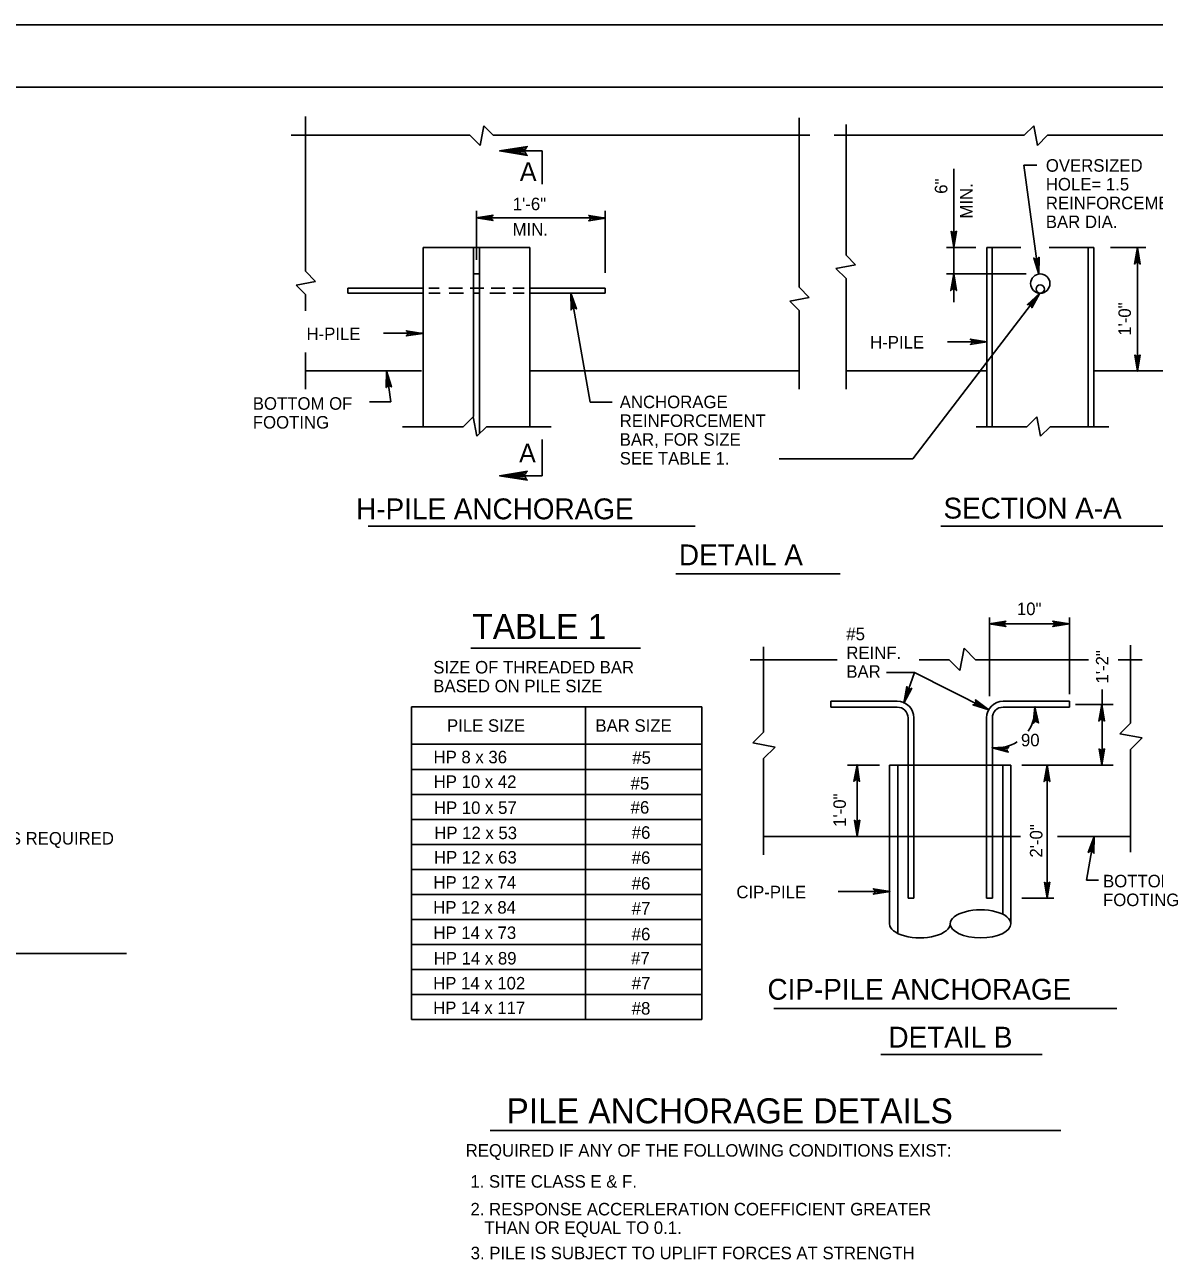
# Model space of a CAD drawing. Extents: x 235 to 2276, y 116 to 1308.
# Drawn here: x 807.5 to 1078.3, y 1007.6 to 1304.4 of the extents above; entities that cross this region are included whole.
import ezdxf

# ---------------------------------------------------------------- set-up
doc = ezdxf.new("R2010")
doc.units = 0
doc.layers.add('1', color=7, linetype='Continuous')
doc.layers.add('PLT-BNDY', color=7, linetype='Continuous')

msp = doc.modelspace()

# ---------------------------------------------------------------- linework, layer by layer
at = {"layer": '1'}
for p, q in [((619.42, 1289.41), (1405.42, 1289.41)), ((874.85, 1282.4), (874.85, 1245.3)), ((916.71, 1275.49), (917.59, 1280.19)), ((917.59, 1280.19), (919.86, 1277.92)), ((993.2, 1282.1), (993.2, 1241.47)), ((1004.46, 1249.13), (1004.46, 1280.51)), ((1049.45, 1280.19), (1047.18, 1277.92)), ((1050.33, 1275.49), (1049.45, 1280.19)), ((871.43, 1277.92), (914.28, 1277.92)), ((914.28, 1277.92), (916.71, 1275.49)), ((919.86, 1277.92), (995.76, 1277.92)), ((1047.18, 1277.92), (1001.63, 1277.92)), ((1052.76, 1277.92), (1050.33, 1275.49)), ((1095.6, 1277.92), (1052.76, 1277.92)), ((921.38, 1274.16), (931.58, 1274.16)), ((931.58, 1266.17), (931.58, 1274.16)), ((1047.03, 1270.76), (1050.19, 1270.76)), ((1047.03, 1270.76), (1050.5, 1245.42)), ((1030.27, 1250.97), (1030.27, 1269.87)), ((915.84, 1248.05), (915.84, 1259.82)), ((946.67, 1244.9), (946.67, 1259.82)), ((915.84, 1258.07), (946.67, 1258.07)), ((903.03, 1250.97), (903.03, 1207.98)), ((903.03, 1250.97), (928.65, 1250.97)), ((915.16, 1250.97), (915.16, 1210.43)), ((915.23, 1250.97), (916.46, 1250.97)), ((916.53, 1250.97), (916.53, 1206.54)), ((928.65, 1250.97), (928.65, 1207.98)), ((1028.52, 1250.97), (1035.59, 1250.97)), ((1030.27, 1244.65), (1030.27, 1250.97)), ((1038.19, 1250.97), (1038.19, 1207.98)), ((1038.19, 1250.97), (1046.38, 1250.97)), ((1039.51, 1250.97), (1039.51, 1207.98)), ((1053.15, 1250.97), (1063.81, 1250.97)), ((1062.49, 1250.97), (1062.49, 1207.98)), ((1063.81, 1250.97), (1063.81, 1207.98)), ((1067.81, 1250.97), (1076.29, 1250.97)), ((1074.31, 1221.39), (1074.31, 1250.97)), ((1002.03, 1245.97), (1006.73, 1246.86)), ((1006.73, 1246.86), (1004.46, 1249.13)), ((874.85, 1245.3), (877.28, 1242.87)), ((915.16, 1244.65), (916.53, 1244.65)), ((1004.46, 1243.54), (1002.03, 1245.97)), ((1028.52, 1244.65), (1047.6, 1244.65)), ((1030.27, 1237.92), (1030.27, 1244.65)), ((877.28, 1242.87), (872.58, 1241.99)), ((872.58, 1241.99), (874.85, 1239.72)), ((885.02, 1241.26), (903.03, 1241.26)), ((885.02, 1241.26), (885.02, 1240.03)), ((904.43, 1241.26), (906.87, 1241.26)), ((909.21, 1241.26), (912.47, 1241.26)), ((914.32, 1241.26), (917.58, 1241.26)), ((919.37, 1241.26), (922.63, 1241.26)), ((924.54, 1241.26), (927.28, 1241.26)), ((928.65, 1241.26), (946.67, 1241.26)), ((946.67, 1241.26), (946.67, 1240.03)), ((993.2, 1241.47), (995.63, 1239.04)), ((1004.46, 1217.04), (1004.46, 1243.54)), ((874.85, 1239.72), (874.85, 1235.82)), ((885.02, 1240.03), (903.03, 1240.03)), ((904.43, 1240.03), (907.11, 1240.03)), ((909.27, 1240.03), (912.72, 1240.03)), ((915.16, 1240.03), (916.53, 1240.03)), ((919, 1240.03), (922.82, 1240.03)), ((924.67, 1240.03), (927.28, 1240.03)), ((928.65, 1240.03), (946.67, 1240.03)), ((943.08, 1213.88), (938.61, 1239.3)), ((995.63, 1239.04), (990.93, 1238.16)), ((990.93, 1238.16), (993.2, 1235.89)), ((1020.47, 1200.33), (1050.7, 1239.89)), ((993.2, 1235.89), (993.2, 1217.04)), ((893.57, 1230.41), (903.03, 1230.41)), ((874.85, 1225.8), (874.85, 1217.04)), ((1028.73, 1228.37), (1038.19, 1228.37)), ((874.85, 1221.39), (902.64, 1221.39)), ((894.3, 1221.39), (895.32, 1213.95)), ((993.2, 1221.39), (928.65, 1221.39)), ((1038.19, 1221.39), (1004.46, 1221.39)), ((1091.84, 1221.39), (1063.81, 1221.39)), ((890.18, 1213.95), (895.32, 1213.95)), ((943.08, 1213.88), (948.34, 1213.88)), ((898.14, 1207.98), (912.62, 1207.98)), ((912.62, 1207.98), (915.05, 1210.41)), ((915.05, 1210.41), (915.93, 1205.71)), ((915.93, 1205.71), (918.2, 1207.98)), ((918.2, 1207.98), (933.76, 1207.98)), ((1035.64, 1207.98), (1047.78, 1207.98)), ((1047.78, 1207.98), (1050.21, 1210.41)), ((1050.21, 1210.41), (1051.09, 1205.71)), ((1051.09, 1205.71), (1053.36, 1207.98)), ((1053.36, 1207.98), (1067.43, 1207.98)), ((931.58, 1204.94), (931.58, 1196.27)), ((988.4, 1200.33), (1020.47, 1200.33)), ((921.38, 1196.27), (931.58, 1196.27)), ((889.84, 1184.15), (968.29, 1184.15)), ((1027.17, 1184.15), (1080.73, 1184.15)), ((1003.06, 1172.74), (963.65, 1172.74)), ((1038.81, 1143.39), (1038.81, 1162.23)), ((1038.81, 1160.74), (1058.02, 1160.74)), ((1058.02, 1143.88), (1058.02, 1162.23)), ((955.18, 1154.88), (914.5, 1154.88)), ((984.67, 1155.21), (984.67, 1134.77)), ((1032.72, 1154.89), (1031.72, 1149.55)), ((1035.48, 1152.13), (1032.72, 1154.89)), ((1072.65, 1155.64), (1072.65, 1136.94)), ((1002.29, 1152.13), (981.45, 1152.13)), ((1029.14, 1152.13), (1022, 1152.13)), ((1031.72, 1149.55), (1029.14, 1152.13)), ((1062.54, 1152.13), (1035.48, 1152.13)), ((1075.43, 1152.13), (1069.64, 1152.13)), ((1020.83, 1149.04), (1014.11, 1149.04)), ((1020.83, 1149.04), (1018.55, 1142.47)), ((1020.83, 1149.04), (1038.25, 1140.25)), ((1065.81, 1126.87), (1065.81, 1144.97)), ((969.9, 1140.84), (900.26, 1140.84)), ((900.26, 1065.84), (900.26, 1140.84)), ((941.99, 1065.84), (941.99, 1140.84)), ((969.9, 1065.84), (969.9, 1140.84)), ((1000.8, 1142.16), (1016.71, 1142.16)), ((1000.8, 1142.16), (1000.8, 1140.76)), ((1000.8, 1140.76), (1016.71, 1140.76)), ((1058.02, 1142.16), (1042.12, 1142.16)), ((1058.02, 1140.76), (1042.12, 1140.76)), ((1058.02, 1142.16), (1058.02, 1140.76)), ((1068.5, 1141.4), (1059.44, 1141.4)), ((1019.31, 1138.16), (1019.31, 1126.87)), ((1020.71, 1138.16), (1020.71, 1126.87)), ((1038.12, 1138.16), (1038.12, 1126.87)), ((1039.52, 1138.16), (1039.52, 1126.87)), ((1070.07, 1134.36), (1072.65, 1136.94)), ((982.09, 1132.19), (984.67, 1134.77)), ((1075.41, 1133.36), (1070.07, 1134.36)), ((969.9, 1131.84), (900.26, 1131.84)), ((987.43, 1131.19), (982.09, 1132.19)), ((984.67, 1128.43), (987.43, 1131.19)), ((1072.65, 1130.6), (1075.41, 1133.36)), ((984.67, 1128.43), (984.67, 1105.34)), ((1072.65, 1130.6), (1072.65, 1105.98)), ((969.9, 1125.84), (900.26, 1125.84)), ((1012.46, 1126.87), (1004.75, 1126.87)), ((1007.07, 1109.75), (1007.07, 1126.87)), ((1043.97, 1126.87), (1014.85, 1126.87)), ((1014.85, 1126.87), (1014.85, 1109.75)), ((1016.82, 1126.87), (1016.82, 1086.5)), ((1019.31, 1126.87), (1019.31, 1094.92)), ((1020.71, 1126.87), (1020.71, 1094.92)), ((1038.12, 1126.87), (1038.12, 1094.92)), ((1039.52, 1126.87), (1039.52, 1094.92)), ((1042, 1126.87), (1042, 1091.08)), ((1043.97, 1126.87), (1043.97, 1109.75)), ((1046.55, 1126.87), (1068.5, 1126.87)), ((1052.64, 1094.92), (1052.64, 1126.87)), ((969.9, 1119.84), (900.26, 1119.84)), ((969.9, 1113.84), (900.26, 1113.84)), ((969.9, 1107.84), (900.26, 1107.84)), ((1046.26, 1109.75), (984.67, 1109.75)), ((1014.85, 1109.75), (1014.85, 1088.79)), ((1043.97, 1109.75), (1043.97, 1088.79)), ((1072.65, 1109.75), (1055.16, 1109.75)), ((1062.05, 1099.25), (1063.92, 1109.75)), ((969.9, 1101.84), (900.26, 1101.84)), ((1064.95, 1099.25), (1062.05, 1099.25)), ((969.9, 1095.84), (900.26, 1095.84)), ((1014.85, 1096.58), (1002.54, 1096.58)), ((1019.31, 1094.92), (1020.71, 1094.92)), ((1039.52, 1094.92), (1038.12, 1094.92)), ((1046.55, 1094.92), (1054.26, 1094.92)), ((969.9, 1089.84), (900.26, 1089.84)), ((969.9, 1083.84), (900.26, 1083.84)), ((639.78, 1081.71), (831.9, 1081.71)), ((969.9, 1077.84), (900.26, 1077.84)), ((969.9, 1071.84), (900.26, 1071.84)), ((987.12, 1068.49), (1069.39, 1068.49)), ((969.9, 1065.84), (900.26, 1065.84)), ((1051.44, 1057.47), (1012.76, 1057.47)), ((919.13, 1039.22), (1055.94, 1039.22))]:
    msp.add_line(p, q, dxfattribs=at)
for points in [[(927.72, 1273.36), (927.49, 1273.82), (921.38, 1274.16), (927.72, 1273.36), (928.05, 1273.08), (921.38, 1274.16), (927.48, 1274.46), (927.71, 1274.91), (921.38, 1274.16), (928.05, 1275.22), (927.71, 1274.91)], [(919.55, 1257.61), (919.43, 1257.86), (915.8, 1258.11), (919.55, 1257.61), (919.8, 1257.49), (915.8, 1258.11), (919.43, 1258.24), (919.55, 1258.49), (915.8, 1258.11), (919.8, 1258.74), (919.55, 1258.49)], [(942.99, 1258.54), (943.12, 1258.29), (946.74, 1258.04), (942.99, 1258.54), (942.74, 1258.67), (946.74, 1258.04), (943.12, 1257.92), (942.99, 1257.54), (946.74, 1258.04), (942.74, 1257.42), (942.99, 1257.54)], [(1030.65, 1254.78), (1030.4, 1254.65), (1030.27, 1251.03), (1030.65, 1254.78), (1030.9, 1254.9), (1030.27, 1251.03), (1030.02, 1254.65), (1029.77, 1254.78), (1030.27, 1251.03), (1029.65, 1254.9), (1029.77, 1254.78)], [(1073.84, 1247.28), (1074.09, 1247.4), (1074.34, 1251.03), (1073.84, 1247.28), (1073.59, 1247.03), (1074.34, 1251.03), (1074.46, 1247.4), (1074.71, 1247.28), (1074.34, 1251.03), (1074.96, 1247.03), (1074.71, 1247.28)], [(1050.58, 1248.43), (1050.33, 1248.25), (1050.62, 1244.62), (1050.58, 1248.43), (1050.72, 1248.64), (1050.62, 1244.62), (1049.95, 1248.2), (1049.67, 1248.29), (1050.62, 1244.62), (1049.46, 1248.47), (1049.67, 1248.29)], [(1029.78, 1240.92), (1030.03, 1241.05), (1030.28, 1244.67), (1029.78, 1240.92), (1029.53, 1240.67), (1030.28, 1244.67), (1030.4, 1241.05), (1030.65, 1240.92), (1030.28, 1244.67), (1030.9, 1240.67), (1030.65, 1240.92)], [(938.66, 1236.24), (938.91, 1236.43), (938.48, 1240.05), (938.66, 1236.24), (938.53, 1236.03), (938.48, 1240.05), (939.28, 1236.5), (939.57, 1236.42), (938.48, 1240.05), (939.79, 1236.25), (939.57, 1236.42)], [(1048.19, 1237.36), (1048.49, 1237.3), (1050.86, 1240.07), (1048.19, 1237.36), (1047.94, 1237.31), (1050.86, 1240.07), (1048.8, 1237.08), (1048.93, 1236.81), (1050.86, 1240.07), (1048.95, 1236.53), (1048.93, 1236.81)], [(899.24, 1230.89), (899.37, 1230.64), (902.99, 1230.39), (899.24, 1230.89), (898.99, 1231.02), (902.99, 1230.39), (899.37, 1230.27), (899.24, 1229.89), (902.99, 1230.39), (898.99, 1229.77), (899.24, 1229.89)], [(1034.48, 1228.84), (1034.61, 1228.59), (1038.23, 1228.34), (1034.48, 1228.84), (1034.23, 1228.97), (1038.23, 1228.34), (1034.61, 1228.22), (1034.48, 1227.84), (1038.23, 1228.34), (1034.23, 1227.72), (1034.48, 1227.84)], [(1074.7, 1225.06), (1074.45, 1224.94), (1074.33, 1221.31), (1074.7, 1225.06), (1074.95, 1225.19), (1074.33, 1221.31), (1074.08, 1224.94), (1073.83, 1225.06), (1074.33, 1221.31), (1073.7, 1225.19), (1073.83, 1225.06)], [(894.34, 1217.6), (894.59, 1217.77), (894.3, 1221.4), (894.34, 1217.6), (894.2, 1217.38), (894.3, 1221.4), (894.97, 1217.83), (895.26, 1217.73), (894.3, 1221.4), (895.46, 1217.55), (895.26, 1217.73)], [(927.72, 1197.06), (927.49, 1196.6), (921.38, 1196.27), (927.72, 1197.06), (928.05, 1197.34), (921.38, 1196.27), (927.48, 1195.97), (927.71, 1195.51), (921.38, 1196.27), (928.05, 1195.21), (927.71, 1195.51)], [(1042.53, 1160.24), (1042.4, 1160.49), (1038.78, 1160.74), (1042.53, 1160.24), (1042.78, 1160.11), (1038.78, 1160.74), (1042.4, 1160.86), (1042.53, 1161.11), (1038.78, 1160.74), (1042.78, 1161.36), (1042.53, 1161.11)], [(1054.23, 1161.23), (1054.36, 1160.98), (1057.98, 1160.73), (1054.23, 1161.23), (1053.98, 1161.35), (1057.98, 1160.73), (1054.36, 1160.6), (1054.23, 1160.23), (1057.98, 1160.73), (1053.98, 1160.1), (1054.23, 1160.23)], [(1019.97, 1145.15), (1019.66, 1145.1), (1018.28, 1141.73), (1019.97, 1145.15), (1020.19, 1145.27), (1018.28, 1141.73), (1019.3, 1145.22), (1019.09, 1145.44), (1018.28, 1141.73), (1018.99, 1145.69), (1019.09, 1145.44)], [(1035.53, 1142.25), (1035.54, 1141.94), (1038.69, 1140.12), (1035.53, 1142.25), (1035.44, 1142.48), (1038.69, 1140.12), (1035.37, 1141.6), (1035.13, 1141.42), (1038.69, 1140.12), (1034.86, 1141.35), (1035.13, 1141.42)], [(1049.45, 1137.07), (1049.72, 1137.22), (1049.72, 1140.87), (1049.45, 1137.07), (1049.3, 1136.87), (1049.72, 1140.87), (1050.1, 1137.25), (1050.37, 1137.13), (1049.72, 1140.87), (1050.57, 1136.94), (1050.37, 1137.13)], [(1065.29, 1137.68), (1065.54, 1137.8), (1065.79, 1141.43), (1065.29, 1137.68), (1065.04, 1137.43), (1065.79, 1141.43), (1065.92, 1137.8), (1066.17, 1137.68), (1065.79, 1141.43), (1066.42, 1137.43), (1066.17, 1137.68)], [(1043.18, 1130.15), (1043.07, 1130.44), (1039.47, 1131.01), (1043.18, 1130.15), (1043.36, 1129.96), (1039.47, 1131.01), (1043.11, 1130.82), (1043.27, 1131.07), (1039.47, 1131.01), (1043.49, 1131.23), (1043.27, 1131.07)], [(1066.12, 1130.62), (1065.87, 1130.5), (1065.75, 1126.87), (1066.12, 1130.62), (1066.37, 1130.75), (1065.75, 1126.87), (1065.5, 1130.5), (1065.25, 1130.62), (1065.75, 1126.87), (1065.12, 1130.75), (1065.25, 1130.62)], [(1006.57, 1123.2), (1006.82, 1123.33), (1007.07, 1126.95), (1006.57, 1123.2), (1006.32, 1122.95), (1007.07, 1126.95), (1007.2, 1123.33), (1007.45, 1123.2), (1007.07, 1126.95), (1007.7, 1122.95), (1007.45, 1123.2)], [(1052.15, 1123.16), (1052.4, 1123.28), (1052.65, 1126.91), (1052.15, 1123.16), (1051.9, 1122.91), (1052.65, 1126.91), (1052.78, 1123.28), (1053.03, 1123.16), (1052.65, 1126.91), (1053.28, 1122.91), (1053.03, 1123.16)], [(1007.46, 1113.49), (1007.21, 1113.37), (1007.09, 1109.74), (1007.46, 1113.49), (1007.71, 1113.62), (1007.09, 1109.74), (1006.84, 1113.37), (1006.59, 1113.49), (1007.09, 1109.74), (1006.46, 1113.62), (1006.59, 1113.49)], [(1062.81, 1106.13), (1063.08, 1106.21), (1063.92, 1109.75), (1062.81, 1106.13), (1062.52, 1105.92), (1063.92, 1109.75), (1063.45, 1106.15), (1063.67, 1105.99), (1063.92, 1109.75), (1063.88, 1105.7), (1063.67, 1105.99)], [(1053.03, 1098.66), (1052.78, 1098.53), (1052.66, 1094.91), (1053.03, 1098.66), (1053.28, 1098.78), (1052.66, 1094.91), (1052.41, 1098.53), (1052.16, 1098.66), (1052.66, 1094.91), (1052.03, 1098.78), (1052.16, 1098.66)], [(1011.23, 1097.06), (1011.36, 1096.81), (1014.98, 1096.56), (1011.23, 1097.06), (1010.98, 1097.19), (1014.98, 1096.56), (1011.36, 1096.44), (1011.23, 1096.06), (1014.98, 1096.56), (1010.98, 1095.94), (1011.23, 1096.06)]]:
    msp.add_lwpolyline(points, dxfattribs=at)
for centre, radius in [((1051, 1242.34), 2.31), ((1051, 1241.03), 0.998)]:
    msp.add_circle(centre, radius, dxfattribs=at)
for centre, radius, start, end in [((1016.71, 1138.16), 4, 0, 90), ((1016.71, 1138.16), 2.6, 0, 90), ((1042.12, 1138.16), 4, 90, 180), ((1042.12, 1138.16), 2.6, 90, 180), ((1040.47, 1140.25), 9.27, 325.6533, 3.1394), ((1040.47, 1140.25), 9.27, 264.1002, 302.8279)]:
    msp.add_arc(centre, radius, start, end, dxfattribs=at)
for centre, major_axis, start_param, end_param in [((1036.69, 1088.79), (7.28, 0), 0, 3.141598), ((1022.13, 1088.79), (-7.28, 0), 0, 3.141593), ((1036.69, 1088.79), (7.28, 0), 3.143175, 6.283185)]:
    msp.add_ellipse(centre, major_axis=major_axis, ratio=0.460563, start_param=start_param, end_param=end_param, dxfattribs=at)
at = {"layer": 'PLT-BNDY'}
msp.add_lwpolyline([(579.42, 1304.41), (1420.42, 1304.41), (1420.42, 710.41), (579.42, 710.41)], close=True, dxfattribs=at)

# ---------------------------------------------------------------- texts
at = {"layer": '1'}
for s, height, p in [('A', 4.5, (926.23, 1266.94)), ('OVERSIZED', 3.003, (1052.34, 1269.17)), ('HOLE= 1.5', 3.003, (1052.34, 1264.67)), ('1\'-6"', 3.003, (924.54, 1259.94)), ('REINFORCEMENT', 3.003, (1052.34, 1260.16)), ('BAR DIA.', 3.003, (1052.34, 1255.66)), (' MIN.', 3.003, (923.38, 1253.85)), ('H-PILE', 3.003, (875.09, 1228.79)), ('H-PILE', 3.003, (1010.21, 1226.76)), ('BOTTOM OF', 3.003, (862.21, 1212.08)), ('ANCHORAGE', 3.003, (950.18, 1212.46)), ('REINFORCEMENT', 3.003, (950.18, 1207.95)), ('FOOTING', 3.003, (862.21, 1207.57)), ('BAR, FOR SIZE', 3.003, (950.18, 1203.45)), ('A', 4.5, (926.05, 1199.43)), ('SEE TABLE 1.', 3.003, (950.18, 1198.94)), (' H-PILE ANCHORAGE', 5, (885.13, 1185.81)), ('SECTION A-A', 5, (1027.8, 1185.98)), ('DETAIL A', 5, (964.37, 1174.77)), ('10"', 3.003, (1045.4, 1162.83)), ('TABLE 1', 6, (914.84, 1157.1)), ('#5', 3, (1004.51, 1156.8)), ('REINF.', 3, (1004.51, 1152.3)), ('SIZE OF THREADED BAR', 3, (905.48, 1148.83)), ('BAR', 3, (1004.51, 1147.8)), ('BASED ON PILE SIZE', 3, (905.48, 1144.33)), ('PILE SIZE', 3, (908.77, 1134.84)), ('BAR SIZE', 3, (944.36, 1134.84)), ('90', 3, (1046.38, 1131.36)), ('HP 8 x 36', 3, (905.54, 1127.29)), ('#5', 3, (953.19, 1127.14)), ('HP 10 x 42', 3, (905.58, 1121.39)), ('#5', 3, (952.8, 1120.98)), ('HP 10 x 57', 3, (905.64, 1115.14)), ('#6', 3, (952.8, 1115.22)), ('AS REQUIRED', 3, (801.28, 1107.8)), ('HP 12 x 53', 3, (905.71, 1109.1)), ('#6', 3, (953.06, 1109.19)), ('HP 12 x 63', 3, (905.64, 1103.25)), ('#6', 3, (953.06, 1103.17)), ('HP 12 x 74', 3, (905.52, 1097.22)), ('#6', 3, (953.06, 1097.01)), ('BOTTOM OF', 3, (1066.06, 1097.54)), ('CIP-PILE', 3, (978.15, 1094.91)), ('FOOTING', 3, (1066.06, 1093.04)), ('HP 12 x 84', 3, (905.46, 1091.24)), ('#7', 3, (953.06, 1090.99)), ('HP 14 x 73', 3, (905.52, 1085.15)), ('#6', 3, (953.06, 1084.83)), ('HP 14 x 89', 3, (905.59, 1079.03)), ('#7', 3, (952.93, 1079.07)), ('HP 14 x 102', 3, (905.45, 1073.05)), ('#7', 3, (953.06, 1073.04)), (' CIP-PILE ANCHORAGE', 5, (983.74, 1070.59)), ('HP 14 x 117', 3, (905.45, 1067.14)), ('#8', 3, (953.06, 1067.02)), ('DETAIL B', 5, (1014.61, 1059.11)), ('PILE ANCHORAGE DETAILS', 6, (923.03, 1040.94)), ('REQUIRED IF ANY OF THE FOLLOWING CONDITIONS EXIST:', 3.003, (913.25, 1032.95)), (' 1. SITE CLASS E & F.', 3.003, (913.25, 1025.51)), (' 2. RESPONSE ACCERLERATION COEFFICIENT GREATER', 3.003, (913.28, 1018.86)), ('    THAN OR EQUAL TO 0.1.', 3.003, (913.28, 1014.42)), (' 3. PILE IS SUBJECT TO UPLIFT FORCES AT STRENGTH', 3.003, (913.33, 1008.35))]:
    msp.add_text(s, height=height, dxfattribs=at).set_placement(p)
for s, height, p in [('6"', 3.003, (1028.73, 1263.87)), (' MIN.', 3.003, (1034.8, 1256.82)), ('1\'-0"', 3.003, (1072.74, 1229.83)), ('1\'-2"', 3, (1067.35, 1146.44)), ('1\'-0"', 3, (1004.4, 1112.06)), ('2\'-0"', 3, (1051.52, 1104.68))]:
    msp.add_text(s, height=height, rotation=90, dxfattribs=at).set_placement(p)

doc.saveas('drawing.dxf')
